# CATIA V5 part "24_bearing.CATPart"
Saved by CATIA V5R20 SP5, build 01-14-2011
Part number: 24_bearing
Bounding box of the stored display mesh (mm): x -19.995 to 19.995, y -49 to -37, z -19.979 to 19.979
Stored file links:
  C:\Documents and Settings\anizard\Bureau\13\24_bearing.CATPart
  C:\Documents and Settings\anizard\Bureau\13\anizard.CATProduct
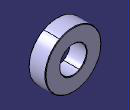
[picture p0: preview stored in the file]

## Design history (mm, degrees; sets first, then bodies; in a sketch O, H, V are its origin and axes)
Set1
  Plane1 to Plane3: linked copy from another document
  Point1: linked copy from another document
  Point2: linked copy from another document
  Line1: linked copy from another document
Body1 (main body)
  Sketch1 on Plane1, origin (0, 0, 0), H (0, 1, 0), V (0, 0, 1)
    line L1 (-48.6464, 20) -> (-37.3536, 20)
    line L2 (-37, 19.6464) -> (-37, 9.8786)
    line L3 (-37.3536, 9.525) -> (-48.6464, 9.525)
    line L4 (-49, 9.8786) -> (-49, 19.6464)
    reference intersected line E1 through (-37, 0) direction (0, 1) from Plane2
    reference intersected line E2 through (-49, 0) direction (0, 1) from Plane3
    reference projected point E3 (0, 9.525) from Point1
    reference projected point E4 (0, 20) from Point2
    line L5 (-37, 9.8786) -> (-37.3536, 9.525)
    line L6 (-48.6464, 9.525) -> (-49, 9.8786)
    line L7 (-37.3536, 20) -> (-37, 19.6464)
    line L8 (-48.6464, 20) -> (-49, 19.6464)
    angle L2 L5 = 45
    length L5 = 0.5
    angle L3 L6 = 45
    length L6 = 0.5
    angle L1 L7 = 45
    length L7 = 0.5
    angle L1 L8 = 45
    length L8 = 0.5
    horizontal: L1 H, L3 H
    vertical: L2 V, L4 V
    coincidence: L2 E1, E2 L4, L3 E3, E4 L1
  Shaft1: profile Sketch1, axis Line1, angle 360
